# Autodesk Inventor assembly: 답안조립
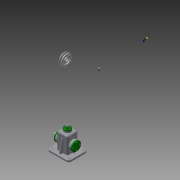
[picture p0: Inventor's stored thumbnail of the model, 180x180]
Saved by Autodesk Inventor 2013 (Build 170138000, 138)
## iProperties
Created: 2016-01
Part Number: 답안조립
Document SubType Name: Assembly
Designer: Administrator
Author: Administrator
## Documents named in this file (19)
- C:\Users\Administrator\Desktop\460127V1001\답안조립.iam
- C:\Users\Administrator\Desktop\460127V1001\1본체.ipt
- C:\Users\Administrator\Desktop\460127V1001\V-벨트풀리.ipt
- C:\Users\Administrator\Desktop\460127V1001\고정핀.ipt
- C:\Users\Administrator\Desktop\460127V1001\뒤커버.ipt
- C:\Users\Administrator\Desktop\460127V1001\링크.ipt
- C:\Users\Administrator\Desktop\460127V1001\멈춤링 6 x 5.ipt
- C:\Users\Administrator\Desktop\460127V1001\멈춤링 15 x 1.ipt
- C:\Users\Administrator\Desktop\460127V1001\베어링 15 x 35 x 11.ipt
- C:\Users\Administrator\Desktop\460127V1001\볼트 M3 x 8.ipt
- C:\Users\Administrator\Desktop\460127V1001\볼트 M4 x 10.ipt
- C:\Users\Administrator\Desktop\460127V1001\볼트 M6 x 12.ipt
- C:\Users\Administrator\Desktop\460127V1001\상부부시.ipt
- C:\Users\Administrator\Desktop\460127V1001\슬라이드바.ipt
- C:\Users\Administrator\Desktop\460127V1001\앞커버.ipt
- C:\Users\Administrator\Desktop\460127V1001\오일실 15 25 7.ipt
- C:\Users\Administrator\Desktop\460127V1001\와셔.ipt
- C:\Users\Administrator\Desktop\460127V1001\키 5 x 5 x 14.ipt
- C:\Users\Administrator\Desktop\460127V1001\편심축.ipt
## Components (16 placed, 6 different names)
1. 1본체:1
2. V-벨트풀리:1
3. 고정핀:1
4. ISO 4018 M6 x 12:1
5. ISO 4762 M4 x 10:1
6. ISO 4762 M4 x 10:3
7. ISO 4762 M4 x 10:4
8. ISO 4762 M4 x 10:5
9. ISO 4762 M4 x 10:2
10. ISO 4762 M4 x 10:6
11. ISO 4762 M4 x 10:7
12. ISO 4762 M4 x 10:8
13. ISO 4762 M3 x 8:1
14. ISO 4762 M3 x 8:2
15. ISO 4762 M3 x 8:3
16. ISO 4762 M3 x 8:4
